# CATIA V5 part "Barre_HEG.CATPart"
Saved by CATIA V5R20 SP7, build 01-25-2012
Part number: Barre_HEG
Bounding box of the stored display mesh (mm): x -155 to 155, y -5 to 5, z 0 to 5
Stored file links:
  D:\IFMA\COURS\2A\projet balance IAO\catia\Barre_HEG.CATPart
  D:\IFMA\COURS\2A\projet balance IAO\catia\Ass_projet_balance.CATProduct
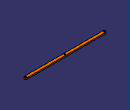
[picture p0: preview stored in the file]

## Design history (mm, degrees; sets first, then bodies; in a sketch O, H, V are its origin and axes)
Set1
  Point1 "Point.H": linked copy from another document
  Point2 "Point.G": linked copy from another document
  Point3 "Point.E": linked copy from another document
Body1 (main body)
  Sketch1 on xy-plane, origin (0, 0, 0), H (1, 0, 0), V (0, 1, 0)
    arc A1 centre (150, 0) radius 5 from (150, -5) to (150, 5) ccw
    point P1 (150, 0)
    arc A2 centre (-150, 0) radius 5 from (-150, 5) to (-150, -5) ccw
    point P4 (-150, 0)
    line L1 (150, 5) -> (-150, 5)
    line L2 (150, -5) -> (-150, -5)
    reference projected point E1 (-150, 0) from Point1
    reference projected point E2 (150, 0) from Point2
    distance L1 L2 = 10
    coincidence: P4 H, P4 E1, P1 E2
    tangency: L1 A1, L2 A1, A2 L1, A2 L2
  Pad1: profile Sketch1, direction (0, 0, 1), length 5
  Sketch2 on start face of Pad1, origin (0, 0, 0), H (1, 0, 0), V (0, -1, 0)
    circle A1 centre (-150, 0) radius 2.5
    point P1 (-150, 0)
    circle A2 centre (0, 0) radius 2.5
    point P2 (0, 0)
    circle A3 centre (150, 0) radius 2.5
    point P3 (150, 0)
    reference projected point E1 (-150, 0) from Point1
    reference projected point E2 (0, 0) from Point3
    reference projected point E3 (150, 0) from Point2
    radius A3 = 2.5
    radius A2 = 2.5
    radius A1 = 2.5
    coincidence: P1 E1, P2 E2, P3 E3
  Pocket1: profile Sketch2, direction (0, 0, 1), through (limit type 6)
